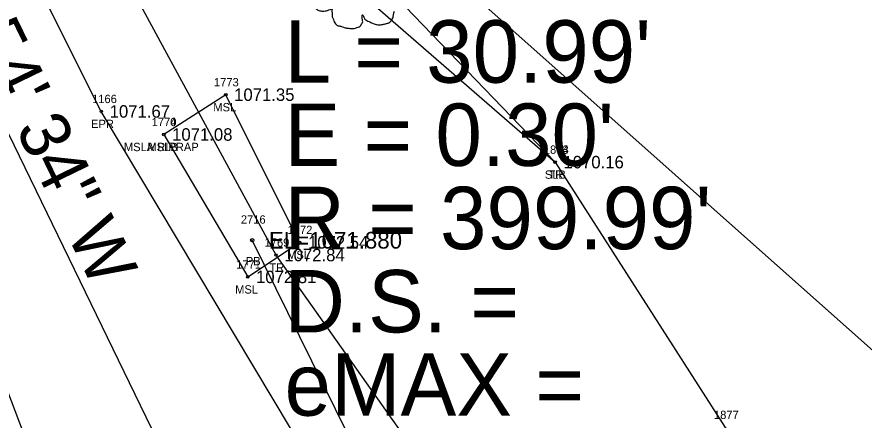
# Model space of a CAD drawing. Extents: x 1578957 to 1581675, y 1115963 to 1120391.
# Drawn here: x 1580415.9 to 1580517.6, y 1116562.5 to 1116610.9 of the extents above; entities that cross this region are included whole.
import ezdxf

# ---------------------------------------------------------------- set-up
doc = ezdxf.new("R2010")
doc.units = 0
for name, color, linetype in [('RD_EX_DR_Pipe', 7, 'Continuous'), ('RD_EX_DR_Pipe_txCode', 7, 'Continuous'), ('RD_EX_Driveway', 7, 'Continuous'), ('RD_EX_Misc', 7, 'Continuous'), ('RD_EX_Misc_txCode', 7, 'Continuous'), ('RD_EX_Road', 7, 'Continuous'), ('RD_EX_Road_txCode', 7, 'Continuous'), ('RD_EX_TX_Misc_ELEV', 7, 'Continuous'), ('RD_EX_TX_Road_ELEV', 7, 'Continuous'), ('RD_EX_TX_VEG_ELEV', 7, 'Continuous'), ('RD_EX_VEG', 7, 'Continuous'), ('RD_EX_VEG_txCode', 7, 'Continuous'), ('RD_HC_Cl', 7, 'Continuous'), ('RD_HC_Data', 7, 'Continuous'), ('RD_SMD_Locator', 7, 'Continuous'), ('RD_TX_Pipe_ElevEX', 7, 'Continuous')]:
    doc.layers.add(name, color=color, linetype=linetype)

msp = doc.modelspace()

# ---------------------------------------------------------------- linework, layer by layer
at = {"layer": 'RD_EX_DR_Pipe'}
msp.add_lwpolyline([(1580531.38, 1116486.91), (1580479.87, 1116511.57), (1580444.12, 1116584.07)], dxfattribs=at)
at = {"layer": 'RD_EX_Driveway'}
msp.add_lwpolyline([(1580448.24, 1116715.43), (1580498.02, 1116671.05), (1580484.73, 1116656.15), (1580483.45, 1116653.45), (1580480, 1116650.21), (1580478.61, 1116649.34), (1580470.01, 1116639.62), (1580479.47, 1116631.06), (1580481.33, 1116627.46), (1580480.2, 1116624.22), (1580470.73, 1116613.48), (1580543.65, 1116548.59)], dxfattribs=at)
at = {"layer": 'RD_EX_Misc'}
msp.add_lwpolyline([(1580433.49, 1116596.78), (1580443.57, 1116579.67), (1580449.81, 1116583.82), (1580440.94, 1116601.56), (1580433.49, 1116596.78)], dxfattribs=at)
at = {"layer": 'RD_EX_Road'}
for points in [[(1580570.71, 1116498.67), (1580529.36, 1116480.65), (1580519.91, 1116479.43), (1580510.64, 1116479.83), (1580504.14, 1116481.67), (1580497.17, 1116485.13), (1580490.27, 1116490.58), (1580483.83, 1116498.29), (1580485.04, 1116499.02), (1580478.37, 1116510.01), (1580451.15, 1116557.41), (1580425.99, 1116599.55), (1580403.29, 1116644.83), (1580382.32, 1116688.41), (1580373.95, 1116705.15), (1580352.79, 1116744.5), (1580332.46, 1116780.72), (1580308.51, 1116820.53), (1580282.29, 1116862.52), (1580254.51, 1116905.2), (1580227.5, 1116946.75), (1580201.69, 1116988.26)], [(1580373.02, 1116418.01), (1580425.37, 1116439.24), (1580432.48, 1116444.21), (1580439.18, 1116451.49), (1580444.63, 1116463.6), (1580445.94, 1116475), (1580444.74, 1116484.46), (1580443.03, 1116489.18), (1580441.49, 1116488.99), (1580438.54, 1116496.4), (1580426.11, 1116533.96), (1580423.22, 1116543.6), (1580405.6, 1116590.01), (1580384.87, 1116635.19), (1580363.63, 1116679.91), (1580314.77, 1116769.46), (1580304.81, 1116786.68), (1580291.3, 1116810.33), (1580264.82, 1116852.68), (1580237.53, 1116894.27), (1580210.3, 1116936.03), (1580183.44, 1116978.21)]]:
    msp.add_lwpolyline(points, dxfattribs=at)
at = {"layer": 'RD_EX_VEG'}
msp.add_line((1580460.55, 1116614.18), (1580480.49, 1116593.46), dxfattribs=at)
msp.add_lwpolyline([(1580554.83, 1116529.8), (1580522.6, 1116521.05), (1580499.55, 1116521.89), (1580486.99, 1116529.01), (1580480.92, 1116539.4), (1580469.38, 1116550.65), (1580446.97, 1116582.3), (1580430.25, 1116613.19), (1580430.92, 1116636.52), (1580480.49, 1116593.46), (1580500.92, 1116561.6), (1580554.83, 1116529.8)], dxfattribs=at)
msp.add_spline([(1580456.97, 1116624.08), (1580456.67, 1116624.1), (1580456.34, 1116624), (1580456.09, 1116623.9), (1580455.87, 1116623.83), (1580455.64, 1116623.73), (1580455.34, 1116623.55), (1580455.12, 1116623.35), (1580454.99, 1116623.1), (1580454.94, 1116622.88), (1580454.89, 1116622.6), (1580454.89, 1116622.43), (1580454.77, 1116622.4), (1580454.62, 1116622.43), (1580454.37, 1116622.5), (1580454.12, 1116622.5), (1580453.87, 1116622.5), (1580453.52, 1116622.48), (1580453.17, 1116622.48), (1580452.89, 1116622.43), (1580452.57, 1116622.38), (1580452.19, 1116622.25), (1580451.84, 1116622.13), (1580451.54, 1116621.88), (1580451.29, 1116621.41), (1580451.17, 1116621.06), (1580451.02, 1116620.81), (1580451.17, 1116620.36), (1580451.34, 1116620.01), (1580451.37, 1116619.81), (1580451.44, 1116619.38), (1580451.54, 1116619.16), (1580451.67, 1116618.96), (1580451.59, 1116618.93), (1580451.22, 1116618.88), (1580450.92, 1116618.78), (1580450.49, 1116618.56), (1580450.27, 1116618.33), (1580450.17, 1116618.01), (1580450.14, 1116617.66), (1580450.04, 1116617.46), (1580449.97, 1116617.18), (1580449.94, 1116617.11), (1580449.89, 1116616.78), (1580449.99, 1116616.33), (1580450.02, 1116615.98), (1580450.14, 1116615.76), (1580450.29, 1116615.58), (1580450.47, 1116615.33), (1580450.87, 1116615.11), (1580451.19, 1116615.01), (1580451.39, 1116614.98), (1580451.22, 1116614.48), (1580451.17, 1116614.13), (1580451.04, 1116613.73), (1580451.04, 1116613.66), (1580450.99, 1116613.18), (1580451.14, 1116612.86), (1580451.22, 1116612.48), (1580451.39, 1116612.26), (1580451.67, 1116611.96), (1580451.99, 1116611.73), (1580452.49, 1116611.61), (1580452.89, 1116611.63), (1580453.47, 1116611.81), (1580453.72, 1116611.88), (1580453.69, 1116611.71), (1580453.72, 1116611.33), (1580453.72, 1116610.91), (1580453.87, 1116610.59), (1580453.97, 1116610.31), (1580454.12, 1116610.06), (1580454.44, 1116609.84), (1580454.84, 1116609.76), (1580455.27, 1116609.61), (1580455.72, 1116609.54), (1580456.22, 1116609.51), (1580456.82, 1116609.66), (1580457.09, 1116609.79), (1580457.19, 1116609.96), (1580457.39, 1116610.34), (1580457.34, 1116610.56), (1580457.37, 1116611.16), (1580457.47, 1116610.98), (1580457.64, 1116610.63), (1580458.14, 1116610.34), (1580458.54, 1116610.16), (1580459.02, 1116610.01), (1580459.32, 1116609.94), (1580459.79, 1116610.01), (1580460.16, 1116610.09), (1580460.54, 1116610.21), (1580460.84, 1116610.49), (1580461.01, 1116610.76), (1580461.06, 1116611.03), (1580461.14, 1116611.41), (1580461.19, 1116611.58)], degree=3, dxfattribs=at)
at = {"layer": 'RD_HC_Cl'}
msp.add_line((1580442.27, 1116540.38), (1580382.63, 1116663.15), dxfattribs=at)
at = {"layer": 'RD_SMD_Locator'}
for centre, radius in [((1580440.94, 1116601.56), 0.15), ((1580425.99, 1116599.55), 0.15), ((1580433.49, 1116596.78), 0.15), ((1580433.49, 1116596.78), 0.15), ((1580480.49, 1116593.46), 0.15), ((1580480.49, 1116593.46), 0.15), ((1580444.12, 1116584.07), 0.2), ((1580449.81, 1116583.82), 0.15), ((1580446.97, 1116582.3), 0.15), ((1580443.57, 1116579.67), 0.15)]:
    msp.add_circle(centre, radius, dxfattribs=at)

# ---------------------------------------------------------------- texts
at = {"layer": 'RD_EX_DR_Pipe_txCode'}
for s, p in [('2716', (1580442.75, 1116586.07)), ('PB', (1580443.34, 1116581.07))]:
    msp.add_text(s, height=1, dxfattribs=at).set_placement(p)
at = {"layer": 'RD_EX_Misc_txCode'}
for s, p in [('1773', (1580439.52, 1116602.56)), ('MSL', (1580439.44, 1116599.56)), ('1770', (1580432.04, 1116597.78)), ('1774', (1580432.04, 1116597.78)), ('MSLA RIPRAP', (1580428.7, 1116594.78)), ('MSLB', (1580431.52, 1116594.78)), ('1772', (1580448.36, 1116584.82)), ('MSL', (1580448.3, 1116581.82)), ('1771', (1580442.18, 1116580.67)), ('MSL', (1580442.06, 1116577.67))]:
    msp.add_text(s, height=1, dxfattribs=at).set_placement(p)
at = {"layer": 'RD_EX_Road_txCode'}
for s, p in [('1166', (1580424.88, 1116600.55)), ('EPR', (1580424.76, 1116597.55))]:
    msp.add_text(s, height=1, dxfattribs=at).set_placement(p)
at = {"layer": 'RD_EX_TX_Misc_ELEV'}
for s, p in [('1071.35', (1580441.94, 1116600.81)), ('1071.08', (1580434.49, 1116596.03)), ('1071.08', (1580434.49, 1116596.03)), ('1072.54', (1580450.81, 1116583.07)), ('1072.81', (1580444.57, 1116578.92))]:
    msp.add_text(s, height=1.5, dxfattribs=at).set_placement(p)
at = {"layer": 'RD_EX_TX_Road_ELEV'}
msp.add_text('1071.67', height=1.5, dxfattribs=at).set_placement((1580426.99, 1116598.8))
at = {"layer": 'RD_EX_TX_VEG_ELEV'}
for s, p in [('1070.16', (1580481.49, 1116592.71)), ('1070.16', (1580481.49, 1116592.71)), ('1072.84', (1580447.97, 1116581.55))]:
    msp.add_text(s, height=1.5, dxfattribs=at).set_placement(p)
at = {"layer": 'RD_EX_VEG_txCode'}
for s, p in [('1873', (1580479.14, 1116594.46)), ('1874', (1580479.14, 1116594.46)), ('SLB', (1580479.26, 1116591.46)), ('TR', (1580479.69, 1116591.46)), ('1769', (1580445.6, 1116583.3)), ('TR', (1580446.17, 1116580.3)), ('1877', (1580499.57, 1116562.6))]:
    msp.add_text(s, height=1, dxfattribs=at).set_placement(p)
at = {"layer": 'RD_HC_Data'}
msp.add_text('N 25%%d 54\' 34" W', height=6, rotation=295.9095, dxfattribs=at).set_placement((1580400.31, 1116629.04))
for s, p in [("L = 30.99'", (1580448, 1116603)), ("E = 0.30'", (1580448, 1116593)), ("R = 399.99'", (1580448, 1116583)), ('D.S. = ', (1580448, 1116573)), ('eMAX = ', (1580448, 1116563))]:
    msp.add_text(s, height=7.5, dxfattribs=at).set_placement(p)
at = {"layer": 'RD_TX_Pipe_ElevEX'}
msp.add_text('EL=1071.880', height=2, dxfattribs=at).set_placement((1580446.12, 1116583.07))

doc.saveas('drawing.dxf')
